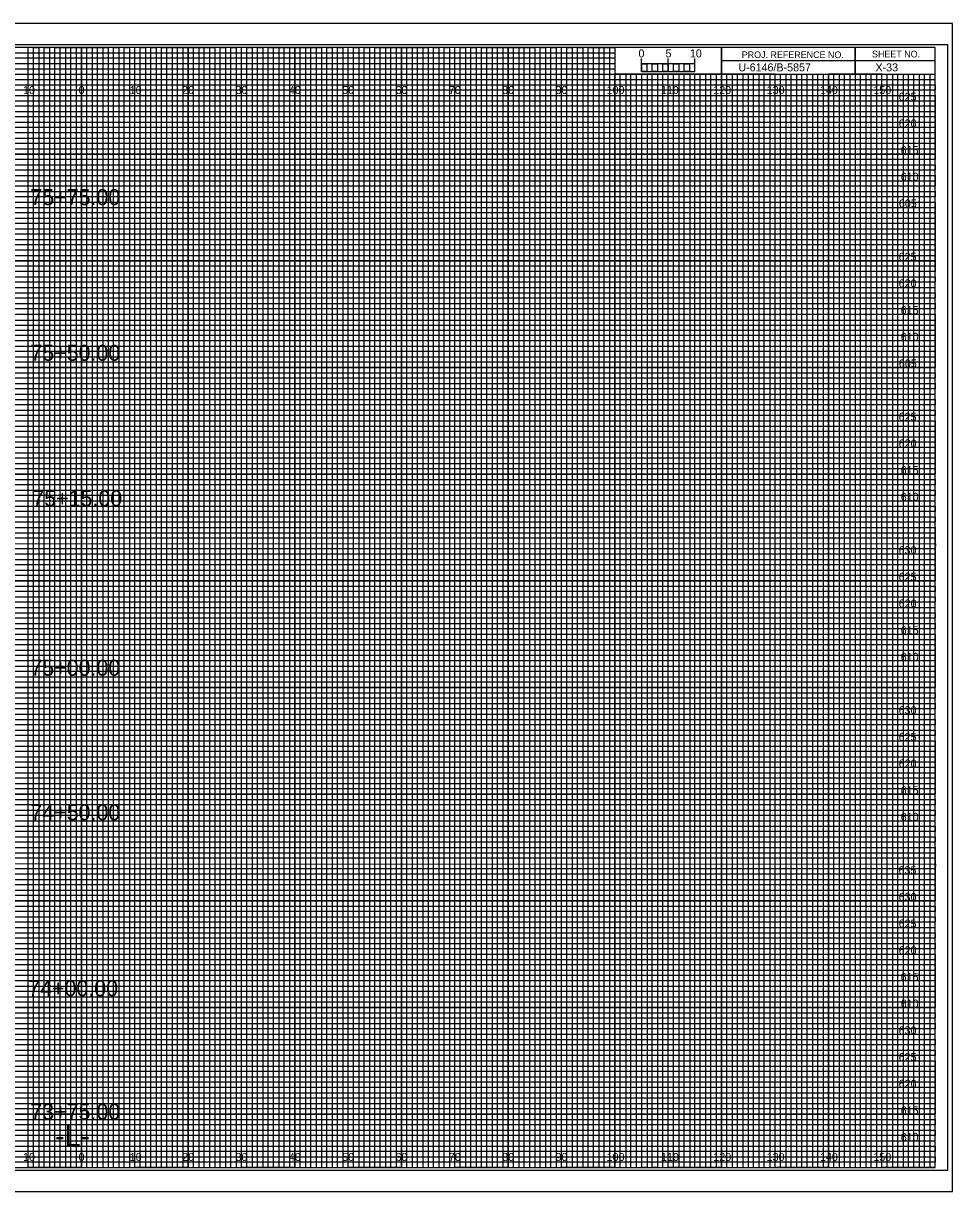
# Model space of a CAD drawing. Extents: x -13 to 323, y 6816 to 7034.
# Drawn here: x 149.1 to 323.3, y 6815.5 to 7034.5 of the extents above; entities that cross this region are included whole.
import ezdxf

# ---------------------------------------------------------------- set-up
doc = ezdxf.new("R2010")
doc.units = 0
for name, color, linetype in [('Exist CMT Alignment Centerline', 7, 'Continuous'), ('Exist XS Center Line Elevation Label', 7, 'Continuous'), ('Exist XS Ground Line', 7, 'Continuous'), ('Prop XS Dump Level', 7, 'Continuous'), ('Prop XS EOT Tick Mark', 7, 'Continuous'), ('Prop XS Finish Grade', 7, 'Continuous'), ('Prop XS Finish Grade CurbGutter', 7, 'Continuous'), ('Prop XS Finish Grade Earthwork', 7, 'Continuous'), ('Prop XS Finish Grade Pavement', 7, 'Continuous'), ('Prop XS Hydro Elevations', 7, 'Continuous'), ('Prop XS Pvmt Edge Slope', 7, 'Continuous'), ('Prop XS SE Text', 7, 'Continuous'), ('Prop XS Side Slope Text', 7, 'Continuous'), ('Prop XS SS Elevation Text', 7, 'Continuous'), ('Prop XS Subgrade CurbGutter', 7, 'Continuous'), ('Prop XS Subgrade Earthwork', 7, 'Continuous'), ('Scratch_Level_3', 7, 'Continuous')]:
    doc.layers.add(name, color=color, linetype=linetype)

msp = doc.modelspace()

# ---------------------------------------------------------------- linework, layer by layer
at = {"layer": 'Exist XS Center Line Elevation Label'}
for p, q in [((150, 7030), (140, 7030)), ((150, 6820), (150, 7030)), ((170, 7030), (160, 7030)), ((160, 7030), (160, 6820)), ((170, 6820), (170, 7030)), ((190, 7030), (180, 7030)), ((180, 7030), (180, 6820)), ((190, 6820), (190, 7030)), ((210, 7030), (200, 7030)), ((200, 7030), (200, 6820)), ((210, 6820), (210, 7030)), ((230, 7030), (220, 7030)), ((220, 7030), (220, 6820)), ((230, 6820), (230, 7030)), ((250, 7030), (240, 7030)), ((240, 7030), (240, 6820)), ((250, 6820), (250, 7030)), ((260, 7030), (260, 6820)), ((270, 6820), (270, 7025)), ((290, 7025), (280, 7025)), ((280, 7025), (280, 6820)), ((290, 6820), (290, 7025)), ((310, 7025), (300, 7025)), ((300, 7025), (300, 6820)), ((310, 6820), (310, 7025)), ((160, 6820), (150, 6820)), ((180, 6820), (170, 6820)), ((200, 6820), (190, 6820)), ((220, 6820), (210, 6820)), ((240, 6820), (230, 6820)), ((260, 6820), (250, 6820)), ((280, 6820), (270, 6820)), ((300, 6820), (290, 6820)), ((320, 6820), (310, 6820)), ((320, 6820), (320, 6820))]:
    msp.add_line(p, q, dxfattribs=at)
for points in [[(0, 7020), (320, 7020), (320, 7010), (0, 7010)], [(0, 7000), (320, 7000), (320, 6990), (0, 6990)], [(0, 6980), (320, 6980), (320, 6970), (0, 6970)], [(0, 6960), (320, 6960), (320, 6950), (0, 6950)], [(0, 6940), (320, 6940), (320, 6930), (0, 6930)], [(0, 6920), (320, 6920), (320, 6910), (0, 6910)], [(0, 6900), (320, 6900), (320, 6890), (0, 6890)], [(0, 6880), (320, 6880), (320, 6870), (0, 6870)], [(0, 6860), (320, 6860), (320, 6850), (0, 6850)], [(0, 6840), (320, 6840), (320, 6830), (0, 6830)]]:
    msp.add_lwpolyline(points, dxfattribs=at)
at = {"layer": 'Prop XS Dump Level'}
for p, q in [((0, 7029), (260, 7029)), ((260, 7027.98), (0, 7027.98)), ((260, 7029), (260, 7027.98)), ((0, 7027), (260, 7027)), ((260, 7025.89), (0, 7025.89)), ((260, 7027), (260, 7025.89)), ((0, 7024), (320, 7024))]:
    msp.add_line(p, q, dxfattribs=at)
for points in [[(0, 7023), (270, 7023), (320, 7023), (320, 7022), (0, 7022)], [(0, 7021), (320, 7021), (320, 7019), (0, 7019)], [(0, 7018), (320, 7018), (320, 7017), (0, 7016.98)], [(0, 7016), (320, 7016), (320, 7014), (0, 7014)], [(0, 7013), (320, 7013), (320, 7012), (0, 7012)], [(0, 7011), (320, 7011), (320, 7009), (0, 7009)], [(0, 7008), (320, 7008), (320, 7007), (0, 7007)], [(0, 7006), (320, 7006), (320, 7004), (0, 7004)], [(0, 7003), (320, 7003), (320, 7002), (0, 7002)], [(0, 7001), (320, 7001), (320, 6999), (0, 6999)], [(0, 6998), (320, 6998), (320, 6997), (0, 6997)], [(0, 6996), (320, 6996), (320, 6993.95), (320, 6993), (320, 6992), (0, 6992)], [(0, 6994), (320, 6994), (320, 6993), (0, 6993)], [(0, 6991), (320, 6991), (320, 6989), (0, 6989.03)], [(0, 6989.03), (320, 6989), (320, 6988), (0, 6988)], [(0, 6987), (320, 6987), (320, 6986), (0, 6986)], [(0, 6984), (320, 6984), (320, 6983), (0, 6983)], [(0, 6982), (320, 6982), (320, 6981), (0, 6981)], [(-0.07, 6978.89), (320, 6978.89), (320, 6977.88), (-0.07, 6977.88)], [(0, 6977), (320, 6977), (320, 6976), (0, 6976)], [(0, 6974), (320, 6974), (320, 6973), (0, 6973)], [(0, 6972), (320, 6972), (320, 6971), (0, 6971)], [(0, 6969), (320, 6969), (320, 6968), (0, 6968)], [(0, 6967), (320, 6967), (320, 6966), (0, 6966)], [(0, 6964), (320, 6964), (320, 6963), (0, 6963)], [(0, 6962), (320, 6962), (320, 6961), (0, 6961)], [(0, 6959), (320, 6959), (319.99, 6957.98), (0, 6958)], [(0, 6957), (320, 6957), (320, 6956), (0, 6956)], [(0, 6954), (320, 6954), (320, 6953), (0, 6953)], [(0, 6952), (320, 6952), (320, 6951), (0, 6951)], [(0, 6949), (320, 6949), (320, 6948), (0, 6948)], [(0, 6947), (320, 6947), (320, 6946), (0, 6946)], [(0, 6944), (320, 6944), (320, 6943), (0, 6943)], [(0, 6942), (320, 6942), (320, 6941), (0, 6941)], [(0, 6939), (320, 6939), (320, 6938), (0, 6938)], [(0, 6936.99), (320.07, 6936.91), (320, 6936), (0, 6936)], [(0, 6934), (320, 6934), (320, 6933), (0, 6933)], [(0, 6932), (320, 6932), (320, 6931), (0, 6931)], [(0, 6929), (320, 6929), (320, 6928), (0, 6928)], [(0, 6927), (320, 6927), (320, 6926), (0, 6926)], [(0, 6924), (320, 6924), (320, 6923), (0, 6923)], [(0, 6922), (320, 6922), (320, 6921), (0, 6921)], [(0, 6919), (320, 6919), (320, 6918), (0, 6918)], [(0, 6917), (320, 6917), (320, 6916), (0, 6916)], [(0, 6914), (320, 6914), (320, 6913), (0, 6913)], [(0, 6912), (320, 6912), (320, 6911), (0, 6911)], [(0, 6909), (320, 6909), (320, 6908), (0, 6908)], [(0, 6907), (320, 6907), (320, 6906), (0, 6906)], [(0, 6904), (320, 6904), (320, 6903), (0, 6903)], [(0, 6902), (320, 6902), (320, 6901), (0, 6901)], [(0, 6899), (320, 6899), (319.99, 6897.98), (0, 6898)], [(0, 6897), (320, 6897), (320, 6896), (0, 6896)], [(0, 6894), (320, 6894), (320, 6893), (0, 6893)], [(0, 6892), (320, 6892), (320, 6891), (0, 6891)], [(0, 6889), (320, 6889), (320, 6888), (0, 6888)], [(0, 6887), (320, 6887), (320, 6886), (0, 6886)], [(0, 6884), (320, 6884), (320, 6883), (0, 6883)], [(0, 6882), (320, 6882), (320, 6881), (0, 6881)], [(0, 6879), (320, 6879), (320, 6878), (0, 6878)], [(0, 6876.99), (320.07, 6876.91), (320, 6876), (0, 6876)], [(0, 6874), (320, 6874), (320, 6873), (0, 6873)], [(0, 6872), (320, 6872), (320, 6871), (0, 6871)], [(0, 6869), (320, 6869), (320, 6868), (0, 6868)], [(0, 6867), (320, 6867), (320, 6866), (0, 6866)], [(0, 6864), (320, 6864), (320, 6863), (0, 6863)], [(0, 6862), (320, 6862), (320, 6861), (0, 6861)], [(0, 6859), (320, 6859), (320, 6858), (0, 6858)], [(0, 6857), (320, 6857), (320, 6856), (0, 6856)], [(0, 6854), (320, 6854), (320, 6853), (0, 6853)], [(0, 6852), (320, 6852), (320, 6851), (0, 6851)], [(0, 6849), (320, 6849), (320, 6848), (0, 6848)], [(0, 6847), (320, 6847), (320, 6846), (0, 6846)], [(0, 6844), (320, 6844), (320, 6843), (0, 6843)], [(0, 6842), (320, 6842), (320, 6841), (0, 6841)], [(0, 6839), (320, 6839), (320, 6838), (0, 6838)], [(0, 6837), (320, 6837), (320, 6836), (0, 6836)], [(0, 6834), (320, 6834), (320, 6833), (0, 6833)], [(0, 6832), (320, 6832), (320, 6831), (0, 6831)], [(0, 6829), (320, 6829), (320, 6828), (0, 6828)], [(0, 6827), (320, 6827), (320, 6826), (0, 6826)], [(0, 6824), (320, 6824), (320, 6823), (0, 6823)], [(0, 6822), (320, 6822), (320, 6821), (0, 6821)]]:
    msp.add_lwpolyline(points, dxfattribs=at)
at = {"layer": 'Prop XS Finish Grade'}
for p, q in [((323.3, 7034.5), (-13.4, 7034.5)), ((-13.4, 6815.5), (323.3, 6815.5))]:
    msp.add_line(p, q, dxfattribs=at)
at = {"layer": 'Prop XS Finish Grade Earthwork'}
msp.add_lwpolyline([(-10.8, 6819.5), (322.4, 6819.5), (322.4, 7030.5), (-10.8, 7030.5)], close=True, dxfattribs=at)
at = {"layer": 'Prop XS Hydro Elevations'}
for p, q in [((267, 7025), (266.01, 7025)), ((266.01, 7025), (266.01, 6820)), ((267, 6820), (267, 7025)), ((269, 7025), (268, 7025)), ((268, 7025), (268, 6820)), ((269, 6820), (269, 7025)), ((266.01, 6820), (265, 6820)), ((268, 6820), (267, 6820))]:
    msp.add_line(p, q, dxfattribs=at)
for points in [[(150, 6820), (151, 6820), (151, 7030), (152, 7030), (152, 6820)], [(152, 6820), (153, 6820), (153, 7030), (154, 7030), (154, 6820)], [(155, 6820), (156, 6820), (156, 7030), (157, 7030), (157, 6820)], [(157, 6820), (158, 6820), (158, 7030), (159, 7030), (159, 6820)], [(160, 6820), (161, 6820), (161, 7030), (162, 7030), (162, 6820)], [(162, 6820), (163, 6820), (163, 7030), (164, 7030), (164, 6820)], [(165, 6820), (166, 6820), (166, 7030), (167, 7030), (167, 6820)], [(167, 6820), (168, 6820), (168, 7030), (169, 7030), (169, 6820)], [(170, 6820), (171, 6820), (171, 7030), (172, 7030), (172, 6820)], [(172, 6820), (173, 6820), (173, 7030), (174, 7030), (174, 6820)], [(175, 6820), (176, 6820), (176, 7030), (177, 7030), (177, 6820)], [(177, 6820), (178, 6820), (178, 7030), (179, 7030), (179, 6820)], [(180, 6820), (181, 6820), (181, 7030), (182, 7030), (182, 6820)], [(182, 6820), (183, 6820), (183, 7030), (184, 7030), (184, 6820)], [(185, 6820), (186, 6820), (186, 7030), (187, 7030), (187, 6820)], [(187, 6820), (188, 6820), (188, 7030), (189, 7030), (189, 6820)], [(190, 6820), (191, 6820), (191, 7030), (192, 7030), (192, 6820)], [(192, 6820), (193, 6820), (193, 7030), (194, 7030), (194, 6820)], [(195, 6820), (196, 6820), (196, 7030), (197, 7030), (197, 6820)], [(197, 6820), (198, 6820), (198, 7030), (199, 7030), (199, 6820)], [(200, 6820), (201, 6820), (201, 7030), (202, 7030), (202, 6820)], [(202, 6820), (203, 6820), (203, 7030), (204, 7030), (204, 6820)], [(205, 6820), (206, 6820), (206, 7030), (207, 7030), (207, 6820)], [(207, 6820), (208, 6820), (208, 7030), (209, 7030), (209, 6820)], [(210, 6820), (211, 6820), (211, 7030), (212, 7030), (212, 6820)], [(212, 6820), (213, 6820), (213, 7030), (214, 7030), (214, 6820)], [(215, 6820), (216, 6820), (216, 7030), (217, 7030), (217, 6820)], [(217, 6820), (218, 6820), (218, 7030), (219, 7030), (219, 6820)], [(220, 6820), (221, 6820), (221, 7030), (222, 7030), (222, 6820)], [(222, 6820), (223, 6820), (223, 7030), (224, 7030), (224, 6820)], [(225, 6820), (226, 6820), (226, 7030), (227, 7030), (227, 6820)], [(227, 6820), (228, 6820), (228, 7030), (229, 7030), (229, 6820)], [(230, 6820), (231, 6820), (231, 7030), (232, 7030), (232, 6820)], [(232, 6820), (233, 6820), (233, 7030), (234, 7030), (234, 6820)], [(235, 6820), (236, 6820), (236, 7030), (237, 7030), (237, 6820)], [(237, 6820), (238, 6820), (238, 7030), (239, 7030), (239, 6820)], [(240, 6820), (241, 6820), (241, 7030), (242, 7030), (242, 6820)], [(242, 6820), (243, 6820), (243, 7030), (244, 7030), (244, 6820)], [(245, 6820), (246, 6820), (246, 7030), (247, 7030), (247, 6820)], [(247, 6820), (248, 6820), (248, 7030), (249, 7030), (249, 6820)], [(250, 6820), (251, 6820), (251, 7030), (252, 7030), (252, 6820)], [(252, 6820), (253, 6820), (253, 7030), (254, 7030), (254, 6820)], [(255, 6820), (256, 6820), (256, 7030), (257, 7030), (257, 6820)], [(257, 6820), (258, 6820), (258, 7030), (259, 7030), (259, 6820)], [(260, 6820), (261, 6820), (261, 7025), (262.02, 7025), (262.02, 6820)], [(262, 6820), (263, 6820), (263, 7025), (263.99, 7025), (263.99, 6820)], [(270, 6820), (270.98, 6820), (270.98, 7025), (272, 7025), (272, 6820)], [(272, 6820), (273, 6820), (273, 7025), (274.05, 7025), (274.05, 6820)], [(275, 6820), (276, 6820), (276, 7025), (277, 7025), (277, 6820)], [(277, 6820), (278, 6820), (278, 7025), (279, 7025), (279, 6820)], [(280, 6820), (281, 6820), (281, 7025), (282, 7025), (282, 6820)], [(282, 6820), (283, 6820), (283, 7025), (284, 7025), (284, 6820)], [(285, 6820), (286, 6820), (286, 7025), (287, 7025), (287, 6820)], [(287, 6820), (288, 6820), (288, 7025), (289, 7025), (289, 6820)], [(290, 6820), (291, 6820), (291, 7025), (292, 7025), (292, 6820)], [(292, 6820), (293, 6820), (293, 7025), (294, 7025), (294, 6820)], [(295, 6820), (296, 6820), (296, 7025), (297, 7025), (297, 6820)], [(297, 6820), (298, 6820), (298, 7025), (299, 7025), (299, 6820)], [(300, 6820), (301, 6820), (301, 7025), (302, 7025), (302, 6820)], [(302, 6820), (303, 6820), (303, 7025), (304, 7025), (304, 6820)], [(305, 6820), (306, 6820), (306, 7025), (307, 7025), (307, 6820)], [(307, 6820), (308, 6820), (308, 7025), (309, 7025), (309, 6820)], [(310, 6820), (311, 6820), (311, 7025), (312, 7025), (312, 6820)], [(312, 6820), (313, 6820), (313, 7025), (314, 7025), (314, 6820)], [(315, 6820), (316, 6820), (316, 7025), (317, 7025), (317, 6820)], [(317, 6820), (318, 6820), (318, 7025), (319, 7025), (319, 6820)]]:
    msp.add_lwpolyline(points, dxfattribs=at)
at = {"layer": 'Prop XS Pvmt Edge Slope'}
for p, q in [((150, 6820), (150, 7030)), ((160, 6820), (160, 7030)), ((170, 6820), (170, 7030)), ((180, 6820), (180, 7030)), ((190, 6820), (190, 7030)), ((200, 6820), (200, 7030)), ((210, 6820), (210, 7030)), ((220, 6820), (220, 7030)), ((230, 6820), (230, 7030)), ((240, 6820), (240, 7030)), ((250, 6820), (250, 7030)), ((260, 6820), (260, 7024.69)), ((270, 6820), (270, 7024.69)), ((280, 6820), (280, 7024.69)), ((290, 6820), (290, 7024.69)), ((300, 6820), (300, 7024.69)), ((310, 6820), (310, 7024.69)), ((0, 7020), (320, 7020)), ((0, 7010), (320, 7010)), ((0, 7000), (320, 7000)), ((0, 6990), (320, 6990)), ((0, 6980), (320, 6980)), ((0, 6970), (320, 6970)), ((0, 6960), (320, 6960)), ((0, 6950), (320, 6950)), ((0, 6940), (320, 6940)), ((0, 6930), (320, 6930)), ((0, 6920), (320, 6920)), ((0, 6910), (320, 6910)), ((0, 6900), (320, 6900)), ((0, 6890), (320, 6890)), ((0, 6880), (320, 6880)), ((0, 6870), (320, 6870)), ((0, 6860), (320, 6860)), ((0, 6850), (320, 6850)), ((0, 6840), (320, 6840)), ((0, 6830), (320, 6830))]:
    msp.add_line(p, q, dxfattribs=at)
at = {"layer": 'Prop XS SE Text'}
for p, q in [((305, 7030), (305, 7025)), ((305, 7025), (305, 7030)), ((280, 7027.5), (280, 7025)), ((320, 7027.49), (280, 7027.49)), ((280, 7025), (320, 7025))]:
    msp.add_line(p, q, dxfattribs=at)
for points in [[(320, 7030), (0, 7030), (0, 6820), (320, 6820)], [(280, 7030), (260, 7030), (260, 7025.03), (280, 7025.03)], [(320, 7030), (280, 7030), (280, 7025), (320, 7025)]]:
    msp.add_lwpolyline(points, close=True, dxfattribs=at)
at = {"layer": 'Prop XS Side Slope Text'}
msp.add_lwpolyline([(-13.4, 6815.5), (323.3, 6815.5), (323.3, 7034.5), (-13.4, 7034.5)], close=True, dxfattribs=at)
at = {"layer": 'Prop XS SS Elevation Text'}
for p, q in [((265, 7025.49), (265, 7027.9)), ((265, 7026.9), (265, 7027.9)), ((270, 7025.49), (270, 7027.9)), ((275, 7025.49), (275, 7027.9)), ((275, 7026.9), (275, 7027.9))]:
    msp.add_line(p, q, dxfattribs=at)
for points in [[(275, 7026.9), (265, 7026.9), (265, 7025.49), (275, 7025.49)], [(265, 7026.9), (266, 7026.9), (266, 7025.49), (265, 7025.49)], [(267, 7026.9), (268, 7026.9), (268, 7025.49), (267, 7025.49)], [(269, 7026.9), (270, 7026.9), (270, 7025.49), (269, 7025.49)], [(271, 7026.9), (272, 7026.9), (272, 7025.49), (271, 7025.49)], [(273, 7026.9), (274, 7026.9), (274, 7025.49), (273, 7025.49)]]:
    msp.add_lwpolyline(points, close=True, dxfattribs=at)
at = {"layer": 'Scratch_Level_3'}
for points in [[(145, 6820), (155, 6820), (155, 7030), (165, 7030), (165, 6820), (175, 6820), (175, 7030), (185, 7030), (185, 6820), (195, 6820), (195, 7030), (205, 7030), (205, 6820), (215, 6820), (215, 7030), (225, 7030), (225, 6820), (235, 6820), (235, 7030), (245, 7030), (245, 6820), (255, 6820), (255, 7030), (259.93, 7030), (260, 7030), (260, 7025), (264.99, 7025), (264.99, 6820), (275, 6820), (275, 7025), (285, 7025), (285, 6820), (295, 6820), (295, 7025), (305, 7025), (305, 6820), (315, 6820), (315, 7025)], [(0, 7025), (275, 7025)], [(0, 7005), (320, 7005), (320, 7015), (0, 7015)], [(0, 6985), (320, 6985), (320, 6995), (0, 6995)], [(0, 6965), (320, 6965), (320, 6975), (0, 6975)], [(0, 6945), (320, 6945), (320, 6955), (0, 6955)], [(0, 6925), (320, 6925), (320, 6935), (0, 6935)], [(0, 6905), (320, 6905), (320, 6915), (0, 6915)], [(0, 6885), (320, 6885), (320, 6895), (0, 6895)], [(0, 6865), (320, 6865), (320, 6875), (0, 6875)], [(0, 6845), (320, 6845), (320, 6855), (0, 6855)], [(0, 6825), (320, 6825), (320, 6835), (0, 6835)]]:
    msp.add_lwpolyline(points, dxfattribs=at)

# ---------------------------------------------------------------- texts
at = {"layer": 'Exist CMT Alignment Centerline'}
for s, p in [('5', (269.47, 7028.12)), ('10', (274.04, 7028.12))]:
    msp.add_text(s, height=1.5, dxfattribs=at).set_placement(p)
at = {"layer": 'Exist XS Ground Line'}
for s, p in [('10', (149.04, 7021.25)), ('0', (159.45, 7021.25)), ('0', (159.45, 7021.25)), ('10', (169.04, 7021.25)), ('20', (178.86, 7021.25)), ('30', (188.86, 7021.25)), ('40', (198.86, 7021.25)), ('50', (208.86, 7021.25)), ('60', (218.86, 7021.25)), ('70', (228.86, 7021.25)), ('80', (238.86, 7021.25)), ('90', (248.86, 7021.25)), ('100', (258.44, 7021.25)), ('110', (268.62, 7021.25)), ('120', (278.44, 7021.25)), ('130', (288.44, 7021.25)), ('140', (298.44, 7021.25)), ('150', (308.44, 7021.25)), ('10', (149.04, 6821.25)), ('0', (159.45, 6821.25)), ('0', (159.45, 6821.25)), ('10', (169.04, 6821.25)), ('20', (178.86, 6821.25)), ('30', (188.86, 6821.25)), ('40', (198.86, 6821.25)), ('50', (208.86, 6821.25)), ('60', (218.86, 6821.25)), ('70', (228.86, 6821.25)), ('80', (238.86, 6821.25)), ('90', (248.86, 6821.25)), ('100', (258.44, 6821.25)), ('110', (268.62, 6821.25)), ('120', (278.44, 6821.25)), ('130', (288.44, 6821.25)), ('140', (298.44, 6821.25)), ('150', (308.44, 6821.25))]:
    msp.add_text(s, height=1.5, dxfattribs=at).set_placement(p)
at = {"layer": 'Prop XS EOT Tick Mark'}
msp.add_text('U-6146/B-5857', height=1.5, dxfattribs=at).set_placement((283.13, 7025.5))
at = {"layer": 'Prop XS Finish Grade CurbGutter'}
msp.add_text('X-33', height=1.5, dxfattribs=at).set_placement((308.83, 7025.5))
at = {"layer": 'Prop XS Finish Grade Pavement'}
msp.add_text('-L-', height=4, dxfattribs=at).set_placement((155.06, 6824))
at = {"layer": 'Prop XS SE Text'}
for s, p in [('PROJ. REFERENCE NO.', (283.77, 7027.99)), ('SHEET NO.', (308.19, 7028.12))]:
    msp.add_text(s, height=1.25, dxfattribs=at).set_placement(p)
at = {"layer": 'Prop XS SS Elevation Text'}
msp.add_text('0', height=1.5, dxfattribs=at).set_placement((264.41, 7028.12))
at = {"layer": 'Prop XS Subgrade CurbGutter'}
for s, p in [('75+75.00', (150.41, 7000.43)), ('75+50.00', (150.41, 6971.25)), ('75+15.00', (150.77, 6943.97)), ('75+00.00', (150.41, 6912.21)), ('74+50.00', (150.41, 6885.11)), ('74+00.00', (150, 6852.13)), ('73+75.00', (150.41, 6828.99))]:
    msp.add_text(s, height=3, dxfattribs=at).set_placement(p)
at = {"layer": 'Prop XS Subgrade Earthwork'}
for s, p in [('625', (313.18, 7020)), ('620', (313.19, 7015)), ('615', (313.55, 7010)), ('610', (313.57, 7005)), ('605', (313.22, 7000)), ('625', (313.18, 6990)), ('620', (313.19, 6985)), ('615', (313.55, 6980)), ('610', (313.57, 6975)), ('605', (313.22, 6970)), ('625', (313.18, 6960)), ('620', (313.19, 6955)), ('615', (313.55, 6950)), ('610', (313.57, 6945)), ('630', (313.18, 6935)), ('625', (313.18, 6930)), ('620', (313.19, 6925)), ('615', (313.55, 6920)), ('610', (313.57, 6915)), ('630', (313.18, 6905)), ('625', (313.18, 6900)), ('620', (313.19, 6895)), ('615', (313.55, 6890)), ('610', (313.57, 6885)), ('635', (313.16, 6875)), ('630', (313.18, 6870)), ('625', (313.18, 6865)), ('620', (313.19, 6860)), ('615', (313.55, 6855)), ('610', (313.57, 6850)), ('630', (313.18, 6844.98)), ('625', (313.18, 6839.98)), ('620', (313.19, 6834.98)), ('615', (313.55, 6829.98)), ('610', (313.57, 6824.98))]:
    msp.add_text(s, height=1.5, dxfattribs=at).set_placement(p)

doc.saveas('drawing.dxf')
